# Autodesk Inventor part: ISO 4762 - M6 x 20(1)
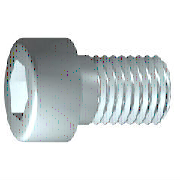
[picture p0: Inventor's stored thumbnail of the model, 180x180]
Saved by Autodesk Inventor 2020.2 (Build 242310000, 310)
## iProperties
Created: 2019-01
Part Number: ISO 4762 - M6 x 20(1)
Material: Acier inoxydable 440C
Description: Vis cylindrique à six pans creux
Document SubType Name: Modeling
Standard: ISO 4762
Designer: Philippe
Standard Revision: Fourth edition 2004-03-01
Standards Organization: ISO
Language: fr-FR
Size Designation: M6 x 20
Categories: <MemberInstance><Categories><Category DisplayName="Visserie" InternalName="e4da775c-781d-43d5-af7c-5136215cf5a6" Mnemonic="FSTN"><Category DisplayName="Vis" Int
Density: 7.75 g/cm^3
Appearance: Semi-poli
IsCustomPart: 0
Author: Philippe
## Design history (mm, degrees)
sketch "Esquisse1"
  geometry: L1 (-1.333, 0)-(20, 0); L2 (20, 0)-(20, 3); L3 (20, 3)-(2.5, 3); L4 (2.5, 3)-(1.886, 3); L5 (1.886, 3)-(0, 3); L6 (0, 3)-(0, 5); L7 (0, 5)-(-6, 5); L8 (-6, 5)-(-6, 2.887); L9 (-6, 2.887)-(-3, 2.887); L10 (-3, 2.887)-(-1.333, 0); L11 (-11.2, 0)-(25.2, 0) reference; L12 (0, -1)-(0, 6) reference; L13 (2.5, 3)-(0, 3)
  constraints: 22 end point, 6 parallel, 2 collinear, 2 perpendicular, 1 horizontal, 1 point on line
  dimensions: "d1" = 17.5 distance from line of L3.end L2 (= GEL); "d2" = 0.61355 distance of L4.end L3.end (computed from GAL); "d3" = 6 distance between parallel lines of L8 L6 (= KOH); "d4" = 3 distance of L8.end L9.end (= INTI); "d5" = 60 deg angle of L10 L1; "d6" = 6 diameter of L3 L1 (= GD); "d7" = 6 diameter of L5 L1 (= BDM); "d8" = 5.7735 diameter of L9 L1 (= 1.1547 x SW); "d9" = 10 diameter of L7 L1 (= KOD); "d26" = 20 distance between parallel lines of L12 L2 (= NLG)
revolve "Corps" sketch "Esquisse1" stored, may be unused: angle "d10" = 90 deg
sketch "Esquisse2"
  geometry: L1 (0, -7)-(0, 7) reference; L2 (-7, 0)-(7, 0) reference; L3 (2.887, 0)-(1.443, -2.5); L4 (1.443, -2.5)-(-1.443, -2.5); L5 (-1.443, -2.5)-(-2.887, 0); L6 (-2.887, 0)-(-1.443, 2.5); L7 (-1.443, 2.5)-(1.443, 2.5); L8 (1.443, 2.5)-(2.887, 0); 2 further points
  constraints: 12 end point, 1 coincident, 1 horizontal alignment, 1 point on line, 12 other
extrude "Rainure" join sketch "Esquisse2" stored distance "d11" = 10; taper "d12" = 0 deg
workplane "Work Plane1"
fillet "Fillet2" dims "d30" = 0.1 (= R)
body "Solid1"
fillet "Congé1" dims "d17" = 0.6 (= RR)
feature "Filetage" dims "d13" = 17.5 (= GEL), "d14" = 0
chamfer "Chanfrein1" distance "d15" = 0.61345 (= -0.5 x SPD + 0.5 x GD); stored, may be unused: second distance "d16" = 0.61345 (= GUL), angle "d27" = 45 deg
other parameters: "GD" = 6 [user parameter; used in 2 equation terms], "NLG" = 20 [user parameter; used in 1 equation term], "GEL" = 17.5 [user parameter; used in 2 equation terms], "KOD" = 10 [user parameter; used in 1 equation term], "KOH" = 6 [user parameter; used in 1 equation term], "INTI" = 3 [user parameter; used in 1 equation term], "GAL" = 0.61345 (= 0.61345 x PTC) [user parameter; used in 1 equation term], "GUL" = 0.61345 (= 0.61345 x PTC) [user parameter; used in 1 equation term], "BDM" = 6 (= NND) [user parameter; used in 1 equation term], "SW" = 5 [user parameter; used in 2 equation terms], "RR" = 0.6 [user parameter; used in 1 equation term], "SPD" = 4.7731 (= NND - 1.2269 x PTC) [user parameter; used in 1 equation term], "d19" = 0, "d28" = 0, "d29" = 0, "R" = 0.1 [user parameter; used in 1 equation term], "TOA" = 30 deg [user parameter], "GD1" = 4.7731 (= THREADDIA - 1.2269 x PTC) [user parameter], "THREADDIA" = 6 [user parameter; used in 1 equation term], "FAWI" = 45 deg [user parameter], "PTC" = 1 [user parameter; used in 5 equation terms], "NND" = 6 [user parameter; used in 2 equation terms], "E0" = 5.775 (= 1.155 x SW) [user parameter]
